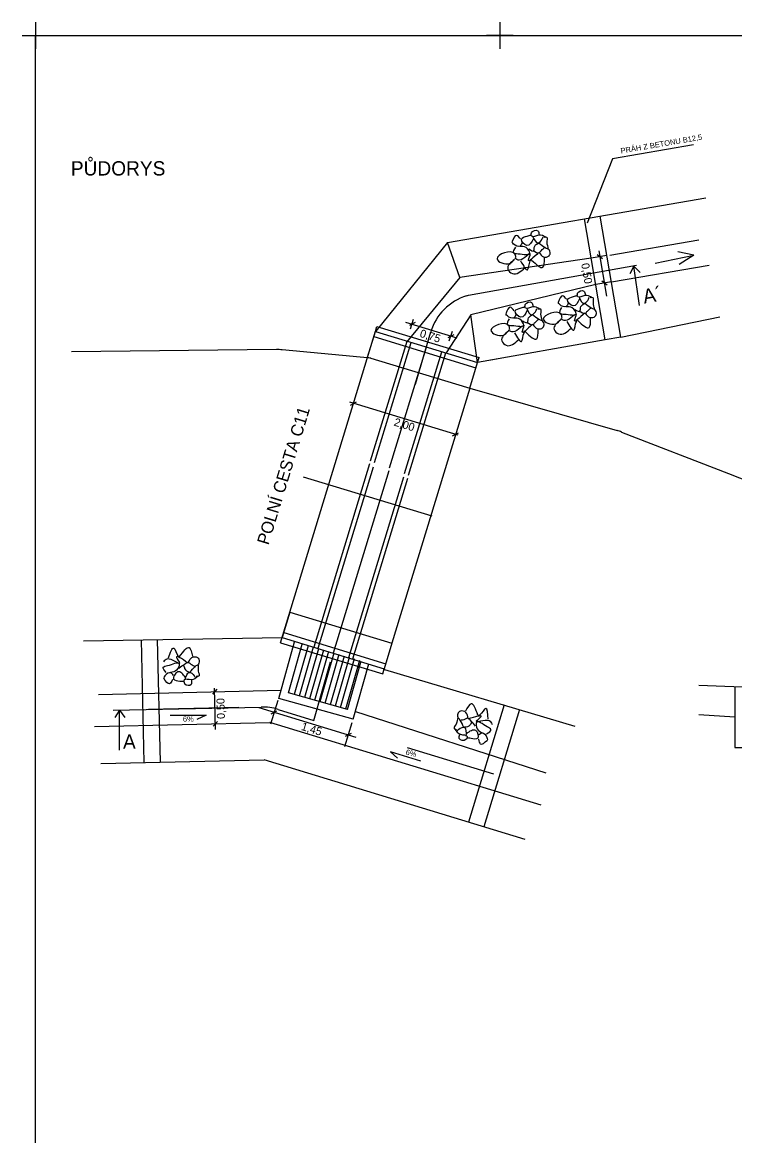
# Model space of a CAD drawing. Extents: x -463095.2 to -463031, y -1105061.3 to -1104976.3.
# Drawn here: x -463091.37 to -463064.66, y -1105018.06 to -1104976.31 of the extents above; entities that cross this region are included whole.
import ezdxf

# ---------------------------------------------------------------- set-up
doc = ezdxf.new("R2010")
doc.units = 0
for name, color, linetype in [('Implicitní', 7, 'Continuous'), ('Vrstva 14', 7, 'Continuous'), ('Vrstva 57', 7, 'Continuous')]:
    doc.layers.add(name, color=color, linetype=linetype)

msp = doc.modelspace()

# ---------------------------------------------------------------- linework, layer by layer
at = {"layer": 'Implicitní'}
for p, q in [((-463073.467, -1104976.311), (-463073.467, -1104977.311)), ((-463073.467, -1104976.311), (-463073.467, -1104977.311)), ((-463072.967, -1104976.811), (-463073.967, -1104976.811)), ((-463072.967, -1104976.811), (-463073.967, -1104976.811))]:
    msp.add_line(p, q, dxfattribs=at)
at = {"layer": 'Vrstva 14'}
for p, q in [((-463090.867, -1104976.312), (-463090.867, -1104977.312)), ((-463091.367, -1104976.812), (-463090.367, -1104976.812)), ((-463066.211, -1104980.908), (-463069.25, -1104981.431)), ((-463069.25, -1104981.431), (-463070.194, -1104983.845)), ((-463075.423, -1104984.567), (-463065.746, -1104982.9)), ((-463069.518, -1104988.217), (-463070.299, -1104983.684)), ((-463068.926, -1104988.116), (-463069.707, -1104983.582)), ((-463075.423, -1104984.567), (-463078.12, -1104987.898)), ((-463074.972, -1104985.88), (-463075.423, -1104984.567)), ((-463069.339, -1104985.047), (-463066.006, -1104984.465)), ((-463069.453, -1104985.061), (-463070.044, -1104985.162)), ((-463069.617, -1104985.18), (-463069.818, -1104985.036)), ((-463069.757, -1104984.886), (-463069.465, -1104986.581)), ((-463067.649, -1104985.338), (-463066.197, -1104985.038)), ((-463066.197, -1104985.038), (-463066.796, -1104984.917)), ((-463066.197, -1104985.038), (-463066.748, -1104985.4)), ((-463070.044, -1104985.162), (-463074.972, -1104985.88)), ((-463069.283, -1104986.046), (-463065.622, -1104985.419)), ((-463068.447, -1104985.454), (-463068.213, -1104985.695)), ((-463074.972, -1104985.88), (-463076.968, -1104988.305)), ((-463069.874, -1104986.148), (-463074.557, -1104987.285)), ((-463069.283, -1104986.046), (-463069.874, -1104986.148)), ((-463069.445, -1104986.163), (-463069.647, -1104986.019)), ((-463077.006, -1104987.551), (-463075.078, -1104988.147)), ((-463076.636, -1104987.567), (-463076.856, -1104987.682)), ((-463076.812, -1104987.812), (-463076.698, -1104987.441)), ((-463074.557, -1104987.285), (-463075.477, -1104988.709)), ((-463074.304, -1104989.073), (-463074.557, -1104987.285)), ((-463068.926, -1104988.116), (-463065.225, -1104987.36)), ((-463081.685, -1104999.578), (-463078.127, -1104987.897)), ((-463078.422, -1104988.864), (-463078.13, -1104987.907)), ((-463078.13, -1104987.907), (-463078.072, -1104987.716)), ((-463078.13, -1104987.907), (-463074.304, -1104989.073)), ((-463078.072, -1104987.716), (-463074.246, -1104988.881)), ((-463076.627, -1104989.881), (-463076.051, -1104987.921)), ((-463075.36, -1104988.261), (-463075.245, -1104987.89)), ((-463078.312, -1104992.759), (-463076.944, -1104988.268)), ((-463078.189, -1104988.098), (-463074.362, -1104989.264)), ((-463078.162, -1104992.815), (-463076.791, -1104988.315)), ((-463075.192, -1104988.028), (-463075.411, -1104988.142)), ((-463069.518, -1104988.217), (-463074.304, -1104989.073)), ((-463068.926, -1104988.116), (-463069.518, -1104988.217)), ((-463081.839, -1104988.584), (-463089.516, -1104988.669)), ((-463078.298, -1104988.912), (-463081.626, -1104988.593)), ((-463077.598, -1104993.024), (-463076.217, -1104988.49)), ((-463077.035, -1104993.235), (-463075.643, -1104988.665)), ((-463076.885, -1104993.292), (-463075.49, -1104988.711)), ((-463078.422, -1104988.864), (-463074.595, -1104990.029)), ((-463074.595, -1104990.029), (-463074.304, -1104989.073)), ((-463074.304, -1104989.073), (-463074.246, -1104988.881)), ((-463073.597, -1104988.946), (-463074.304, -1104989.073)), ((-463074.595, -1104990.029), (-463077.509, -1104999.595)), ((-463074.595, -1104990.029), (-463069.073, -1104991.62)), ((-463075.024, -1104991.791), (-463079.094, -1104990.552)), ((-463079.062, -1104990.664), (-463078.843, -1104990.549)), ((-463075.238, -1104991.823), (-463075.019, -1104991.708)), ((-463068.902, -1104991.677), (-463064.894, -1104993.235)), ((-463078.347, -1104992.874), (-463080.44, -1104999.748)), ((-463078.214, -1104992.987), (-463080.287, -1104999.794)), ((-463080.835, -1104993.355), (-463076.016, -1104994.823)), ((-463077.63, -1104993.129), (-463079.713, -1104999.969)), ((-463077.077, -1104993.371), (-463079.139, -1105000.144)), ((-463076.924, -1104993.418), (-463078.986, -1105000.191)), ((-463064.894, -1104993.235), (-463063.002, -1104993.972)), ((-463081.335, -1104998.43), (-463081.627, -1104999.386)), ((-463081.335, -1104998.43), (-463077.509, -1104999.595)), ((-463081.568, -1104999.195), (-463077.742, -1105000.361)), ((-463081.629, -1104999.391), (-463089.074, -1104999.517)), ((-463086.913, -1104999.473), (-463086.806, -1105004.072)), ((-463086.311, -1104999.459), (-463086.204, -1105004.058)), ((-463081.756, -1105001.669), (-463081.162, -1104999.536)), ((-463081.685, -1104999.578), (-463081.627, -1104999.386)), ((-463081.685, -1104999.578), (-463077.858, -1105000.743)), ((-463081.627, -1104999.386), (-463077.8, -1105000.552)), ((-463081.386, -1105001.46), (-463080.875, -1104999.624)), ((-463080.654, -1104999.689), (-463081.177, -1105001.52)), ((-463077.509, -1104999.595), (-463077.8, -1105000.552)), ((-463080.461, -1104999.744), (-463080.985, -1105001.575)), ((-463080.269, -1104999.799), (-463080.793, -1105001.63)), ((-463080.077, -1104999.854), (-463080.6, -1105001.685)), ((-463079.885, -1104999.909), (-463080.408, -1105001.74)), ((-463079.692, -1104999.964), (-463080.216, -1105001.795)), ((-463079.5, -1105000.019), (-463080.023, -1105001.85)), ((-463079.308, -1105000.074), (-463079.831, -1105001.905)), ((-463079.115, -1105000.129), (-463079.639, -1105001.96)), ((-463078.923, -1105000.184), (-463079.446, -1105002.015)), ((-463078.731, -1105000.239), (-463079.254, -1105002.07)), ((-463079.171, -1105002.077), (-463078.676, -1105000.301)), ((-463078.962, -1105002.447), (-463078.382, -1105000.362)), ((-463077.858, -1105000.743), (-463077.8, -1105000.552)), ((-463077.796, -1105000.574), (-463070.66, -1105002.7)), ((-463088.516, -1105001.511), (-463081.667, -1105001.352)), ((-463084.069, -1105001.32), (-463084.239, -1105001.5)), ((-463084.13, -1105002.827), (-463084.166, -1105001.276)), ((-463066.009, -1105001.161), (-463055.449, -1105001.616)), ((-463064.664, -1105001.219), (-463064.664, -1105002.281)), ((-463081.792, -1105001.737), (-463082.065, -1105002.633)), ((-463078.962, -1105002.447), (-463081.756, -1105001.669)), ((-463079.171, -1105002.077), (-463081.386, -1105001.46)), ((-463087.956, -1105002.106), (-463082.415, -1105001.987)), ((-463087.718, -1105002.11), (-463087.521, -1105002.383)), ((-463086.639, -1105002.068), (-463083.254, -1105001.989)), ((-463078.849, -1105003.125), (-463082.492, -1105002.016)), ((-463082.04, -1105002.241), (-463081.821, -1105002.126)), ((-463071.734, -1105004.469), (-463078.86, -1105002.172)), ((-463073.306, -1105001.9), (-463074.646, -1105006.301)), ((-463072.73, -1105002.075), (-463074.07, -1105006.476)), ((-463064.664, -1105001.947), (-463064.664, -1105002.369)), ((-463088.664, -1105002.715), (-463082.085, -1105002.562)), ((-463084.048, -1105002.529), (-463084.217, -1105002.709)), ((-463071.915, -1105005.669), (-463082.085, -1105002.562)), ((-463079.018, -1105002.582), (-463079.291, -1105003.478)), ((-463064.664, -1105002.369), (-463066.014, -1105002.281)), ((-463064.664, -1105002.281), (-463064.664, -1105003.503)), ((-463079.251, -1105003.078), (-463079.032, -1105002.963)), ((-463073.692, -1105004.5), (-463076.931, -1105003.514)), ((-463064.664, -1105003.503), (-463064.062, -1105003.503)), ((-463088.426, -1105004.11), (-463082.306, -1105003.968)), ((-463072.52, -1105006.948), (-463082.306, -1105003.968))]:
    msp.add_line(p, q, dxfattribs=at)
msp.add_lwpolyline([(-463090.867, -1105060.811), (-463090.867, -1104976.812), (-463031.467, -1104976.812), (-463031.467, -1105060.811)], close=True, dxfattribs=at)
for points in [[(-463074.715, -1104986.572), (-463074.644, -1104986.55), (-463068.343, -1104985.421)], [(-463068.233, -1104986.933), (-463068.447, -1104985.454), (-463068.588, -1104985.749)], [(-463081.773, -1105002.078), (-463080.439, -1105002.497), (-463079.808, -1105000.29)], [(-463087.718, -1105003.604), (-463087.718, -1105002.11), (-463087.9, -1105002.383)], [(-463085.829, -1105002.286), (-463084.48, -1105002.286), (-463084.824, -1105002.45)], [(-463076.425, -1105004.021), (-463077.565, -1105003.67), (-463077.304, -1105003.901)]]:
    msp.add_lwpolyline(points, dxfattribs=at)
for centre, start, end in [((-463074.132, -1104988.485), 106.9595, 163.6136), ((-463081.817, -1104990.584), 84.5379, 90.6298), ((-463069.627, -1104993.541), 68.7557, 73.9322), ((-463082.372, -1105003.986), 72.5665, 91.2363)]:
    msp.add_arc(centre, 2, start, end, dxfattribs=at)
for points in [[(-463071.738, -1104984.377), (-463072.016, -1104984.293), (-463072.272, -1104984.337), (-463072.283, -1104984.207), (-463072.044, -1104984.129), (-463071.995, -1104984.277)], [(-463072.698, -1104984.435), (-463072.84, -1104984.303), (-463073.013, -1104984.548)], [(-463072.636, -1104984.58), (-463072.711, -1104984.701), (-463072.95, -1104984.634), (-463073.011, -1104984.56)], [(-463072.209, -1104984.421), (-463072.453, -1104984.68), (-463072.658, -1104984.452), (-463072.44, -1104984.329), (-463072.29, -1104984.291)], [(-463072.381, -1104984.812), (-463072.19, -1104984.875), (-463072.176, -1104984.753), (-463072.035, -1104984.596)], [(-463072.237, -1104984.331), (-463072.037, -1104984.584), (-463071.874, -1104984.424), (-463071.848, -1104984.359)], [(-463072.013, -1104984.58), (-463071.656, -1104984.783), (-463071.694, -1104984.562), (-463071.7, -1104984.382), (-463071.809, -1104984.377)], [(-463072.864, -1104985.135), (-463072.91, -1104984.984), (-463073.569, -1104985.177), (-463073.104, -1104985.355), (-463072.947, -1104985.228)], [(-463072.884, -1104984.743), (-463072.955, -1104984.96), (-463072.781, -1104984.989), (-463072.341, -1104984.974), (-463072.486, -1104984.757), (-463072.721, -1104984.714)], [(-463072.012, -1104984.941), (-463072.394, -1104985.222), (-463072.325, -1104984.995), (-463072.739, -1104985.233), (-463072.909, -1104985.155)], [(-463072.224, -1104984.864), (-463071.986, -1104984.949), (-463071.916, -1104984.876), (-463071.758, -1104984.741)], [(-463071.997, -1104984.945), (-463071.826, -1104985.112), (-463071.619, -1104985.065), (-463071.58, -1104984.938), (-463071.666, -1104984.78)], [(-463072.913, -1104985.202), (-463073.165, -1104985.564), (-463072.998, -1104985.732), (-463072.522, -1104985.512)], [(-463072.688, -1104985.261), (-463072.426, -1104985.589), (-463072.329, -1104985.26), (-463072.291, -1104985.192)], [(-463072.274, -1104985.232), (-463071.853, -1104985.497), (-463071.795, -1104985.15)], [(-463070.006, -1104986.642), (-463070.285, -1104986.558), (-463070.541, -1104986.602), (-463070.551, -1104986.472), (-463070.313, -1104986.394), (-463070.263, -1104986.542)], [(-463070.966, -1104986.699), (-463071.109, -1104986.568), (-463071.282, -1104986.813)], [(-463070.477, -1104986.686), (-463070.721, -1104986.945), (-463070.927, -1104986.717), (-463070.708, -1104986.594), (-463070.559, -1104986.556)], [(-463070.505, -1104986.596), (-463070.305, -1104986.849), (-463070.142, -1104986.689), (-463070.117, -1104986.624)], [(-463070.282, -1104986.845), (-463069.924, -1104987.047), (-463069.962, -1104986.827), (-463069.969, -1104986.647), (-463070.077, -1104986.642)], [(-463072.929, -1104987.125), (-463073.071, -1104986.993), (-463073.244, -1104987.238)], [(-463072.44, -1104987.112), (-463072.683, -1104987.371), (-463072.889, -1104987.142), (-463072.671, -1104987.019), (-463072.521, -1104986.981)], [(-463071.968, -1104987.067), (-463072.247, -1104986.983), (-463072.503, -1104987.027), (-463072.513, -1104986.897), (-463072.275, -1104986.819), (-463072.225, -1104986.967)], [(-463072.468, -1104987.021), (-463072.268, -1104987.275), (-463072.104, -1104987.115), (-463072.079, -1104987.049)], [(-463072.244, -1104987.271), (-463071.886, -1104987.473), (-463071.924, -1104987.252), (-463071.931, -1104987.073), (-463072.04, -1104987.067)], [(-463071.132, -1104987.4), (-463071.178, -1104987.249), (-463071.837, -1104987.442), (-463071.372, -1104987.62), (-463071.215, -1104987.493)], [(-463070.905, -1104986.845), (-463070.979, -1104986.965), (-463071.218, -1104986.899), (-463071.28, -1104986.824)], [(-463071.153, -1104987.008), (-463071.223, -1104987.225), (-463071.049, -1104987.254), (-463070.61, -1104987.239), (-463070.754, -1104987.022), (-463070.989, -1104986.979)], [(-463070.28, -1104987.206), (-463070.662, -1104987.487), (-463070.594, -1104987.26), (-463071.007, -1104987.498), (-463071.177, -1104987.42)], [(-463070.65, -1104987.077), (-463070.458, -1104987.14), (-463070.445, -1104987.017), (-463070.303, -1104986.861)], [(-463070.492, -1104987.129), (-463070.255, -1104987.214), (-463070.184, -1104987.141), (-463070.027, -1104987.006)], [(-463070.265, -1104987.21), (-463070.095, -1104987.377), (-463069.888, -1104987.329), (-463069.849, -1104987.203), (-463069.935, -1104987.045)], [(-463073.094, -1104987.825), (-463073.14, -1104987.675), (-463073.799, -1104987.867), (-463073.334, -1104988.045), (-463073.177, -1104987.919)], [(-463072.867, -1104987.27), (-463072.942, -1104987.391), (-463073.18, -1104987.324), (-463073.242, -1104987.25)], [(-463073.115, -1104987.433), (-463073.185, -1104987.65), (-463073.012, -1104987.679), (-463072.572, -1104987.664), (-463072.717, -1104987.447), (-463072.951, -1104987.405)], [(-463072.612, -1104987.502), (-463072.42, -1104987.565), (-463072.407, -1104987.443), (-463072.266, -1104987.287)], [(-463072.455, -1104987.555), (-463072.217, -1104987.639), (-463072.146, -1104987.566), (-463071.989, -1104987.432)], [(-463072.228, -1104987.635), (-463072.057, -1104987.803), (-463071.85, -1104987.755), (-463071.811, -1104987.628), (-463071.897, -1104987.471)], [(-463071.181, -1104987.467), (-463071.433, -1104987.829), (-463071.266, -1104987.997), (-463070.791, -1104987.777)], [(-463070.956, -1104987.526), (-463070.694, -1104987.854), (-463070.597, -1104987.525), (-463070.56, -1104987.457)], [(-463070.543, -1104987.497), (-463070.122, -1104987.761), (-463070.064, -1104987.415)], [(-463073.143, -1104987.892), (-463073.396, -1104988.254), (-463073.229, -1104988.423), (-463072.753, -1104988.203)], [(-463072.243, -1104987.632), (-463072.624, -1104987.913), (-463072.556, -1104987.686), (-463072.97, -1104987.923), (-463073.139, -1104987.845)], [(-463072.918, -1104987.951), (-463072.657, -1104988.279), (-463072.559, -1104987.95), (-463072.522, -1104987.883)], [(-463072.505, -1104987.922), (-463072.084, -1104988.187), (-463072.026, -1104987.84)], [(-463085.47, -1105000.096), (-463085.108, -1104999.755), (-463084.984, -1105000.085)], [(-463085.157, -1105000.331), (-463085.585, -1105000.129), (-463085.474, -1105000.338), (-463085.926, -1105000.185), (-463086.078, -1105000.294)], [(-463085.881, -1105000.147), (-463085.688, -1104999.775), (-463085.528, -1105000.079), (-463085.479, -1105000.138)], [(-463085.143, -1105000.324), (-463085.007, -1105000.127), (-463084.795, -1105000.134), (-463084.732, -1105000.251), (-463084.786, -1105000.422)], [(-463085.974, -1105000.694), (-463086.085, -1105000.494), (-463085.92, -1105000.432), (-463085.486, -1105000.362), (-463085.586, -1105000.603), (-463085.808, -1105000.69)], [(-463085.494, -1105000.529), (-463085.318, -1105000.43), (-463085.282, -1105000.548), (-463085.113, -1105000.674)], [(-463085.35, -1105000.447), (-463085.133, -1105000.318), (-463085.049, -1105000.376), (-463084.869, -1105000.478)], [(-463085.088, -1105000.685), (-463084.776, -1105000.418), (-463084.771, -1105000.642), (-463084.743, -1105000.819), (-463084.849, -1105000.846)], [(-463085.7, -1105000.805), (-463085.796, -1105000.702), (-463086.018, -1105000.813), (-463086.064, -1105000.898)], [(-463085.732, -1105000.96), (-463085.847, -1105001.117), (-463086.063, -1105000.91)], [(-463085.25, -1105000.879), (-463085.539, -1105000.672), (-463085.697, -1105000.935), (-463085.459, -1105001.014), (-463085.305, -1105001.022)], [(-463084.779, -1105000.832), (-463085.036, -1105000.968), (-463085.296, -1105000.974), (-463085.281, -1105001.104), (-463085.032, -1105001.134), (-463085.011, -1105000.98)], [(-463085.26, -1105000.973), (-463085.112, -1105000.686), (-463084.921, -1105000.811), (-463084.884, -1105000.871)], [(-463074.664, -1105002.419), (-463074.741, -1105002.193), (-463074.947, -1105002.142), (-463075.039, -1105002.238), (-463075.033, -1105002.417)], [(-463074.287, -1105002.287), (-463074.544, -1105001.862), (-463074.752, -1105002.145)], [(-463073.905, -1105002.447), (-463073.991, -1105002.036), (-463074.226, -1105002.287), (-463074.289, -1105002.33)], [(-463074.813, -1105002.752), (-463075.042, -1105002.41), (-463075.107, -1105002.625), (-463075.182, -1105002.788), (-463075.087, -1105002.842)], [(-463074.497, -1105002.593), (-463074.671, -1105002.41), (-463074.767, -1105002.444), (-463074.968, -1105002.493)], [(-463074.38, -1105002.71), (-463074.523, -1105002.568), (-463074.59, -1105002.671), (-463074.787, -1105002.747)], [(-463074.652, -1105002.429), (-463074.185, -1105002.349), (-463074.348, -1105002.521), (-463073.871, -1105002.495), (-463073.755, -1105002.641)], [(-463073.962, -1105002.998), (-463073.802, -1105002.836), (-463073.944, -1105002.732), (-463074.343, -1105002.548), (-463074.311, -1105002.806), (-463074.121, -1105002.95)], [(-463075.151, -1105002.81), (-463074.94, -1105003.01), (-463074.691, -1105003.086), (-463074.74, -1105003.207), (-463074.988, -1105003.169), (-463074.966, -1105003.015)], [(-463074.726, -1105003.075), (-463074.79, -1105002.759), (-463075.008, -1105002.828), (-463075.06, -1105002.875)], [(-463074.71, -1105002.982), (-463074.376, -1105002.86), (-463074.294, -1105003.156), (-463074.545, -1105003.168), (-463074.696, -1105003.135)], [(-463074.257, -1105003.032), (-463074.136, -1105002.958), (-463073.952, -1105003.125), (-463073.931, -1105003.219)], [(-463074.267, -1105003.19), (-463074.199, -1105003.372), (-463073.934, -1105003.231)]]:
    msp.add_spline(points, degree=3, dxfattribs=at)

# ---------------------------------------------------------------- texts
for s, p in [('PŮDORYS', (-463089.547, -1104982.057)), ('A', (-463087.592, -1105003.551))]:
    msp.add_text(s, height=0.536, dxfattribs=at).set_placement(p)
for s, height, rotation, p in [('0,50', 0.3, 279.7756, (-463070.42, -1104985.369)), ('A´', 0.536, 10.3108, (-463068.054, -1104986.864)), ('0,75', 0.3, 342.8458, (-463076.491, -1104988.102)), ('2,00', 0.3, 343.0608, (-463077.461, -1104991.427)), ('0,50', 0.3, 91.3295, (-463083.771, -1105002.43)), ('1,45', 0.3, 343.0608, (-463080.936, -1105002.84))]:
    msp.add_text(s, height=height, rotation=rotation, dxfattribs=at).set_placement(p)
at = {"layer": 'Vrstva 57'}
for s, height, rotation, p in [('PRÁH Z BETONU B12,5', 0.204, 9.7756, (-463068.923, -1104981.237)), ('POLNÍ CESTA C11', 0.459, 73.0608, (-463082.139, -1104995.936)), ('6%', 0.204, 345.9558, (-463077.014, -1105003.765))]:
    msp.add_text(s, height=height, rotation=rotation, dxfattribs=at).set_placement(p)
msp.add_text('6%', height=0.204, dxfattribs=at).set_placement((-463085.347, -1105002.536))

doc.saveas('drawing.dxf')
